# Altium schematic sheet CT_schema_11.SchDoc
size 297 x 239 mm
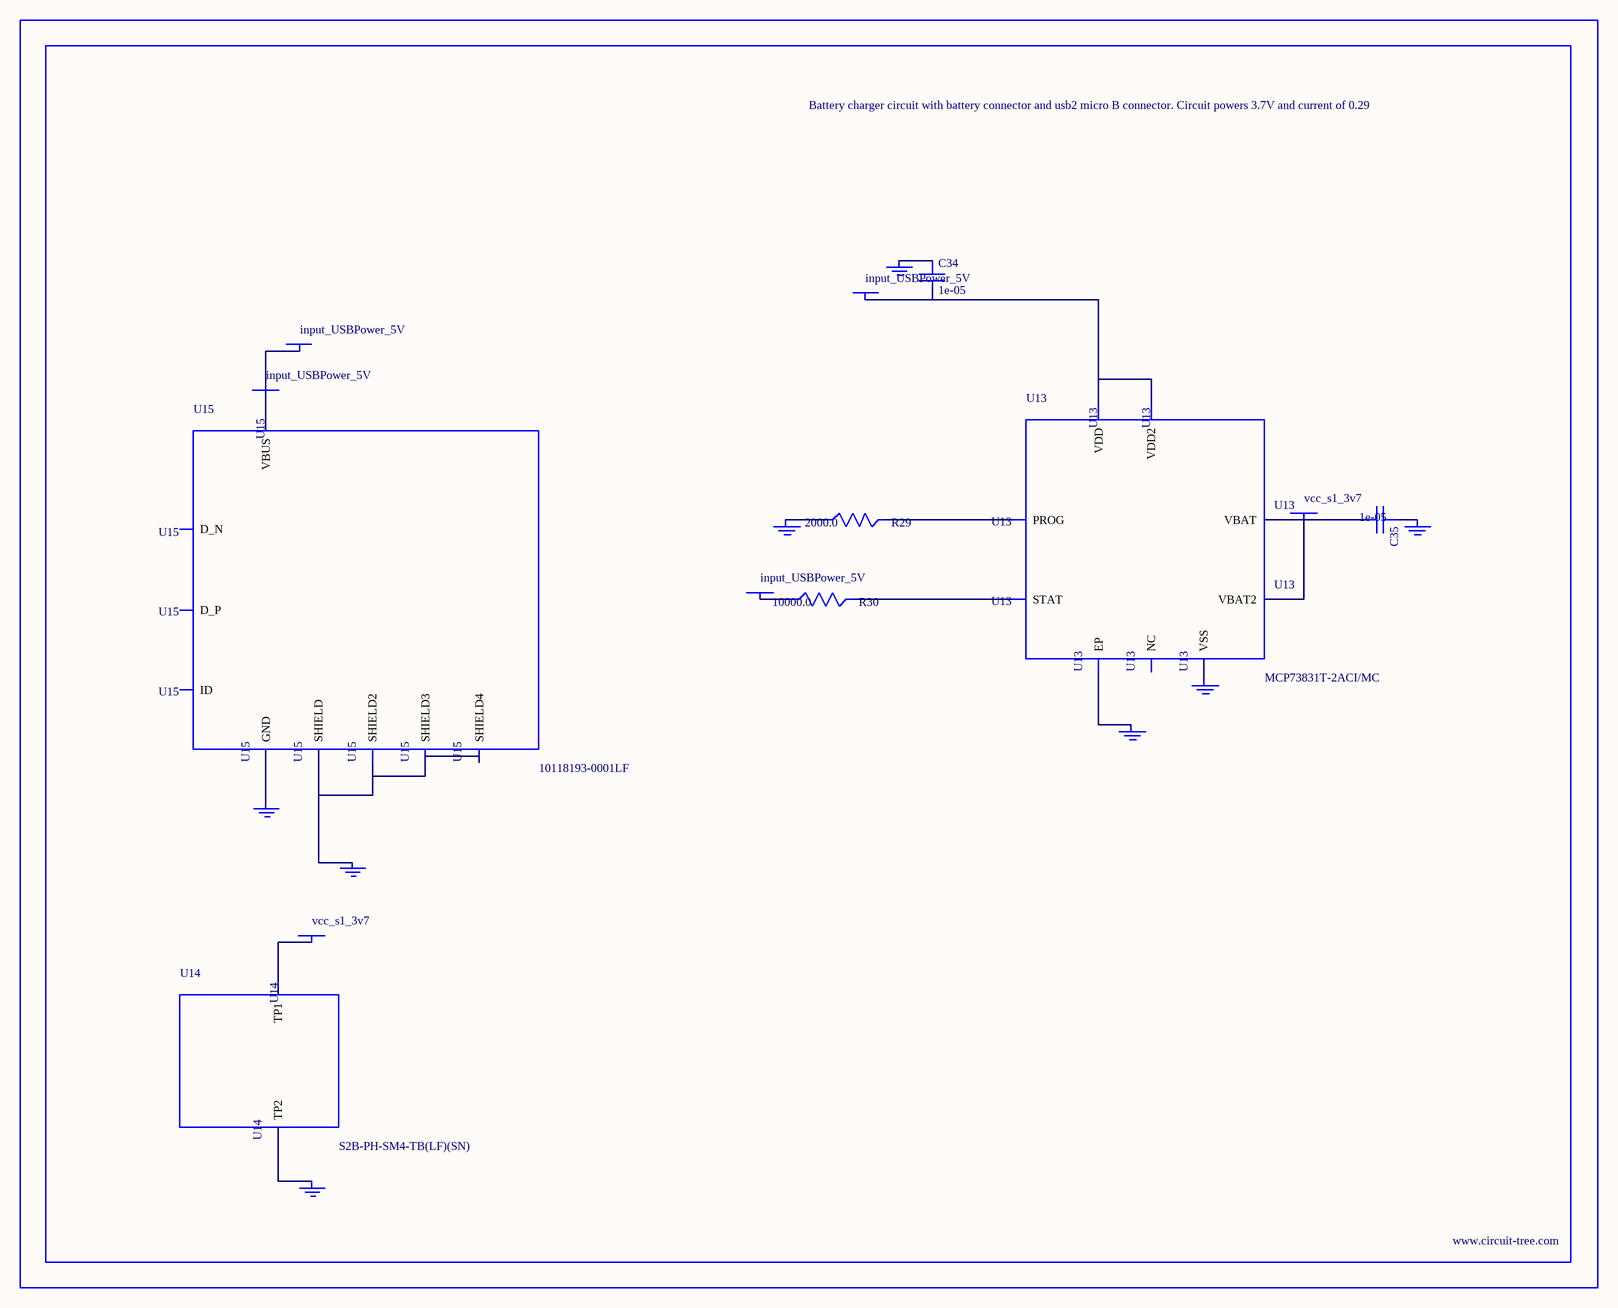
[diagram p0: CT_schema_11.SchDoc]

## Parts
BORDER10  (no value)
C34  1e-05  [C1206]
C35  1e-05  [C1206]
GND_INSTANCE_10_0  (no value)
GND_INSTANCE_10_1  (no value)
GND_INSTANCE_10_2  (no value)
GND_INSTANCE_10_3  (no value)
GND_INSTANCE_10_4  (no value)
GND_INSTANCE_10_5  (no value)
GND_INSTANCE_10_6  (no value)
GND_INSTANCE_10_7  (no value)
POWER_INSTANCE_10_0  input_USBPower_5V
POWER_INSTANCE_10_1  input_USBPower_5V
POWER_INSTANCE_10_2  vcc_s1_3v7
POWER_INSTANCE_10_3  vcc_s1_3v7
POWER_INSTANCE_10_4  input_USBPower_5V
POWER_INSTANCE_10_5  input_USBPower_5V
R29  2000.0  [R0603]
R30  10000.0  [R0603]
U13  MCP73831T-2ACI/MC  [DFN8_2X3MC]
U14  S2B-PH-SM4-TB(LF)(SN)  [JST-2-SMD]
U15  10118193-0001LF  [FCI_10118193-0001LF]

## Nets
NetC34_1: C34.1 GND_INSTANCE_10_0.0(GND)
NetC34_2: C34.2 POWER_INSTANCE_10_0.0(PWR) U13.1(VDD) U13.2(VDD2)
NetC35_1: C35.1 GND_INSTANCE_10_1.0(GND)
NetC35_2: C35.2 POWER_INSTANCE_10_2.0(PWR) U13.3(VBAT) U13.4(VBAT2)
NetGND_INSTANCE_10_2_0: GND_INSTANCE_10_2.0(GND) R29.1
NetGND_INSTANCE_10_3_0: GND_INSTANCE_10_3.0(GND) U13.9(EP)
NetGND_INSTANCE_10_4_0: GND_INSTANCE_10_4.0(GND) U13.6(VSS)
NetGND_INSTANCE_10_5_0: GND_INSTANCE_10_5.0(GND) U14.2(TP2)
NetGND_INSTANCE_10_6_0: GND_INSTANCE_10_6.0(GND) U15.6(SHIELD) U15.7(SHIELD2) U15.8(SHIELD3) U15.9(SHIELD4)
NetGND_INSTANCE_10_7_0: GND_INSTANCE_10_7.0(GND) U15.5(GND)
NetPOWER_INSTANCE_10_1_0: POWER_INSTANCE_10_1.0(PWR) R30.1
NetPOWER_INSTANCE_10_3_0: POWER_INSTANCE_10_3.0(PWR) U14.1(TP1)
NetPOWER_INSTANCE_10_4_0: POWER_INSTANCE_10_4.0(PWR) POWER_INSTANCE_10_5.0(PWR) U15.1(VBUS)
NetR29_2: R29.2 U13.8(PROG)
NetR30_2: R30.2 U13.5(STAT)

Not connected (* = marked no-connect by the designer): U13 7(NC); U15 2(D_N) 3(D_P) 4(ID)

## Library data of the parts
BORDER10 = BORDER_PAGE10
C34 C35 = C1206C106K3RACTU
GND_INSTANCE_10_0-GND_INSTANCE_10_7 = GND
POWER_INSTANCE_10_0-POWER_INSTANCE_10_5 = PWR
R29 = RC0603JR-072KL
R30 = RC0603JR-0710KL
